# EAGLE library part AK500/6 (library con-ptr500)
CONNECTOR
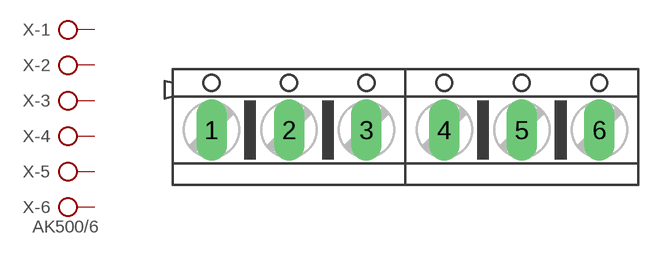
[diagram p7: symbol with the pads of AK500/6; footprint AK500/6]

Designator prefix X; gates -1=KL -2=KL -3=KL -4=KL -5=KL -6=KLV

## AK500/6 (OC_FARNELL: unknown; OC_NEWARK: unknown)  [AK500/6]
1  -1:KL  pas
2  -2:KL  pas
3  -3:KL  pas
4  -4:KL  pas
5  -5:KL  pas
6  -6:KL  pas

## Footprint AK500/6 (pad centres in mm)
CONNECTOR
drill 1.321 long: 1 -12.522,0; 2 -7.518,0; 3 -2.515,0; 4 2.515,0; 5 7.518,0; 6 12.522,0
